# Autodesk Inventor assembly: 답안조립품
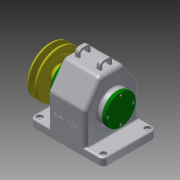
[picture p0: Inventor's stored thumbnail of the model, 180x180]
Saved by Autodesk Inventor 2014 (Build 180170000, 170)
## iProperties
Created: 2016-12
Part Number: 답안조립품
Document SubType Name: Assembly
Designer: USER
Author: USER
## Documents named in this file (15)
- C:\Users\USER\Desktop\461208V1020\답안조립품.iam
- C:\Users\USER\Desktop\461208V1020\본체.ipt
- C:\Users\USER\Desktop\461208V1020\앞커버.ipt
- C:\Users\USER\Desktop\461208V1020\뒤커버.ipt
- C:\Users\USER\Desktop\461208V1020\베어링 6203.ipt
- C:\Users\USER\Desktop\461208V1020\축.ipt
- C:\Users\USER\Desktop\461208V1020\키 - 6 x 6 x 22.ipt
- C:\Users\USER\Desktop\461208V1020\키 - 5 x 5 x 18.ipt
- C:\Users\USER\Desktop\461208V1020\스퍼기어.ipt
- C:\Users\USER\Desktop\461208V1020\부시.ipt
- C:\Users\USER\Desktop\461208V1020\V-벨트풀리.ipt
- C:\Users\USER\Desktop\461208V1020\멈춤나사 - M4x10.ipt
- C:\Users\USER\Desktop\461208V1020\볼트 M3 x 8.ipt
- C:\Users\USER\Desktop\461208V1020\볼트 M3 x 10.ipt
- C:\Users\USER\Desktop\461208V1020\오일씰 28 40 8.ipt
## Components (9 placed, 3 different names)
1. V-벨트풀리:1
2. ISO 4762 M3 x 8:1
3. ISO 4762 M3 x 8:2
4. ISO 4762 M3 x 8:3
5. ISO 4762 M3 x 8:4
6. ISO 4762 M3 x 10:1
7. ISO 4762 M3 x 10:2
8. ISO 4762 M3 x 10:3
9. ISO 4762 M3 x 10:4
